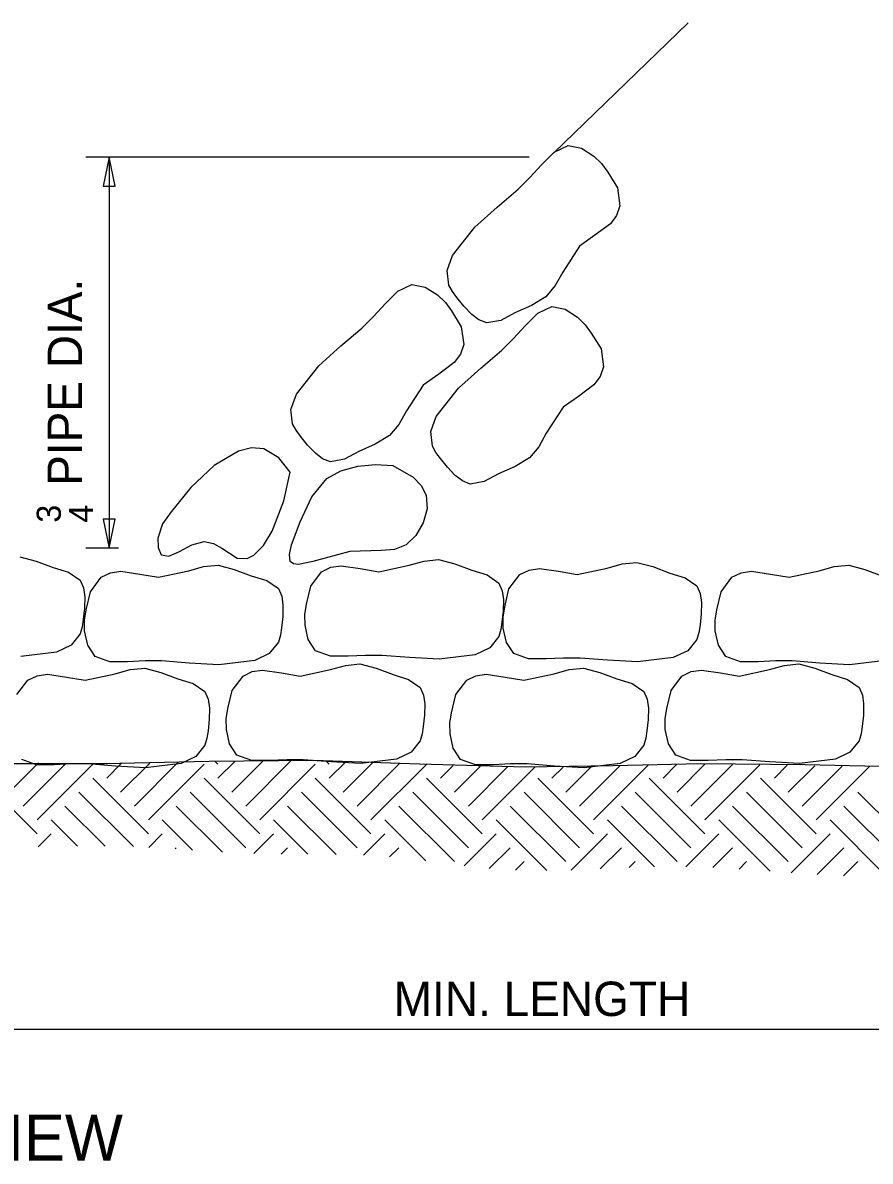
# Model space of a CAD drawing. Extents: x -439.1 to -407.9, y -458.1 to -436.2.
# Drawn here: x -428.606 to -424.913, y -444.35 to -439.387 of the extents above; entities that cross this region are included whole.
import ezdxf

# ---------------------------------------------------------------- set-up
doc = ezdxf.new("R2010")
doc.units = 0
doc.layers.add('Level 4', color=7, linetype='Continuous')

msp = doc.modelspace()

# ---------------------------------------------------------------- linework, layer by layer
at = {"layer": 'Level 4'}
for p, q in [((-426.2933, -439.9554), (-425.7067, -439.3867)), ((-426.3997, -439.973), (-428.3314, -439.973)), ((-428.2285, -439.973), (-428.2285, -441.6773)), ((-428.1891, -441.6773), (-428.3314, -441.6773)), ((-428.6643, -442.741), (-428.5371, -442.6138)), ((-428.1794, -442.741), (-428.0525, -442.6141)), ((-428.1187, -442.8016), (-427.9282, -442.6111)), ((-427.7551, -442.6197), (-427.7676, -442.6072)), ((-427.7551, -442.6804), (-427.6801, -442.6054)), ((-427.6944, -442.741), (-427.5572, -442.6037)), ((-427.6338, -442.8016), (-427.4355, -442.6033)), ((-427.2701, -442.6197), (-427.2849, -442.6049)), ((-427.2701, -442.6804), (-427.1967, -442.6069)), ((-427.2095, -442.741), (-427.0795, -442.611)), ((-428.6037, -442.8016), (-428.4176, -442.6156)), ((-428.543, -442.8622), (-428.3006, -442.6197)), ((-428.24, -442.6197), (-428.2417, -442.618)), ((-428.24, -442.6804), (-428.1764, -442.6168)), ((-428.0581, -442.8622), (-427.8157, -442.6197)), ((-427.5732, -442.8622), (-427.3308, -442.6197)), ((-427.1489, -442.8016), (-426.9629, -442.6155)), ((-427.0883, -442.8622), (-426.8464, -442.6203)), ((-426.7852, -442.6804), (-426.7299, -442.625)), ((-426.7246, -442.741), (-426.6124, -442.6288)), ((-426.664, -442.8016), (-426.4938, -442.6313)), ((-426.6034, -442.8622), (-426.3736, -442.6324)), ((-426.3003, -442.6804), (-426.2515, -442.6316)), ((-426.2397, -442.741), (-426.1279, -442.6292)), ((-426.1791, -442.8016), (-426.0036, -442.6261)), ((-426.1185, -442.8622), (-425.879, -442.6227)), ((-425.8154, -442.6804), (-425.7549, -442.6198)), ((-425.7548, -442.741), (-425.6323, -442.6184)), ((-425.6942, -442.8016), (-425.5129, -442.6203)), ((-425.6336, -442.8622), (-425.3936, -442.6222)), ((-425.3305, -442.6804), (-425.2743, -442.6241)), ((-425.2699, -442.741), (-425.1549, -442.626)), ((-425.2093, -442.8016), (-425.0356, -442.6279)), ((-425.1487, -442.8622), (-424.9163, -442.6298)), ((-428.543, -442.9228), (-428.7855, -442.6804)), ((-428.0581, -442.9228), (-428.3006, -442.6804)), ((-427.5732, -442.9228), (-427.8157, -442.6804)), ((-427.0883, -442.9228), (-427.3308, -442.6804)), ((-426.6034, -442.9228), (-426.8458, -442.6804)), ((-426.1185, -442.9228), (-426.3609, -442.6804)), ((-425.6336, -442.9228), (-425.876, -442.6804)), ((-425.1487, -442.9228), (-425.3911, -442.6804)), ((-428.1234, -442.9787), (-428.3612, -442.741)), ((-427.6338, -442.9834), (-427.8763, -442.741)), ((-427.1489, -442.9834), (-427.3914, -442.741)), ((-426.664, -442.9834), (-426.9065, -442.741)), ((-426.1791, -442.9834), (-426.4215, -442.741)), ((-425.6942, -442.9834), (-425.9366, -442.741)), ((-425.2093, -442.9834), (-425.4517, -442.741)), ((-424.7244, -442.9834), (-424.9668, -442.741)), ((-428.2468, -442.9766), (-428.4218, -442.8016)), ((-427.7356, -443.0029), (-427.9369, -442.8016)), ((-427.2407, -443.0128), (-427.452, -442.8016)), ((-426.7246, -443.044), (-426.9671, -442.8016)), ((-426.2397, -443.044), (-426.4822, -442.8016)), ((-425.7548, -443.044), (-425.9972, -442.8016)), ((-425.2699, -443.044), (-425.5123, -442.8016)), ((-424.785, -443.044), (-425.0274, -442.8016)), ((-428.3675, -442.9772), (-428.4824, -442.8622)), ((-427.8656, -442.9941), (-427.9975, -442.8622)), ((-427.3632, -443.0117), (-427.5126, -442.8622)), ((-426.8488, -443.0411), (-427.0277, -442.8622)), ((-426.3216, -443.0834), (-426.5428, -442.8622)), ((-425.853, -443.0671), (-426.0579, -442.8622)), ((-425.3493, -443.0858), (-425.5729, -442.8622)), ((-424.8456, -443.1047), (-425.088, -442.8622)), ((-428.5388, -442.9792), (-428.4824, -442.9228)), ((-428.0565, -442.9818), (-427.9975, -442.9228)), ((-427.5985, -443.0087), (-427.5126, -442.9228)), ((-427.1213, -443.0164), (-427.0277, -442.9228)), ((-426.6822, -443.0622), (-426.5428, -442.9228)), ((-426.2163, -443.0813), (-426.0579, -442.9228)), ((-425.7166, -443.0665), (-425.5729, -442.9228)), ((-425.2578, -443.0926), (-425.088, -442.9228)), ((-427.9421, -442.9887), (-427.9369, -442.9834)), ((-427.4795, -443.0109), (-427.452, -442.9834)), ((-427.0072, -443.0236), (-426.9671, -442.9834)), ((-426.5727, -443.0739), (-426.4822, -442.9834)), ((-426.0897, -443.0759), (-425.9972, -442.9834)), ((-425.5989, -443.07), (-425.5123, -442.9834)), ((-425.1443, -443.1003), (-425.0274, -442.9834)), ((-426.4586, -443.0811), (-426.4215, -443.044)), ((-425.9629, -443.0704), (-425.9366, -443.044)), ((-425.484, -443.0763), (-425.4517, -443.044)), ((-425.029, -443.1062), (-424.9668, -443.044)), ((-431.8697, -443.7744), (-420.5223, -443.7744))]:
    msp.add_line(p, q, dxfattribs=at)
for points in [[(-426.0567, -440.038), (-426.0141, -440.1066), (-426.0033, -440.1844), (-426.018, -440.2267), (-426.0451, -440.2634), (-426.1124, -440.3132), (-426.1799, -440.3609), (-426.253, -440.4735), (-426.2856, -440.5328), (-426.3263, -440.5817), (-426.3889, -440.6188), (-426.461, -440.6514), (-426.5232, -440.6841), (-426.5842, -440.6955), (-426.6181, -440.6819), (-426.6492, -440.6583), (-426.6836, -440.6226), (-426.7143, -440.584), (-426.7337, -440.5579), (-426.7491, -440.5306), (-426.7562, -440.467), (-426.7326, -440.4009), (-426.6353, -440.2773), (-426.5383, -440.1905), (-426.4471, -440.1123), (-426.3964, -440.0616), (-426.3448, -440.0055), (-426.2903, -439.9509), (-426.2287, -439.9218), (-426.1713, -439.9337), (-426.1171, -439.9683), (-426.0834, -440.0009), (-426.0567, -440.038)], [(-428.2023, -440.0995), (-428.2285, -439.973), (-428.2548, -440.0995)], [(-426.7376, -440.6432), (-426.695, -440.7118), (-426.6842, -440.7896), (-426.6989, -440.832), (-426.726, -440.8686), (-426.7933, -440.9184), (-426.8608, -440.9662), (-426.9339, -441.0788), (-426.9665, -441.138), (-427.0071, -441.1869), (-427.0698, -441.2241), (-427.1419, -441.2566), (-427.2041, -441.2893), (-427.2651, -441.3008), (-427.299, -441.2872), (-427.3301, -441.2636), (-427.3645, -441.2278), (-427.3952, -441.1892), (-427.4146, -441.1631), (-427.43, -441.1358), (-427.4371, -441.0723), (-427.4134, -441.0061), (-427.3162, -440.8825), (-427.2192, -440.7958), (-427.128, -440.7176), (-427.0773, -440.6668), (-427.0257, -440.6107), (-426.9712, -440.5562), (-426.9096, -440.5271), (-426.8522, -440.5389), (-426.798, -440.5735), (-426.7643, -440.6061), (-426.7376, -440.6432)], [(-426.1283, -440.7403), (-426.0857, -440.8089), (-426.0749, -440.8867), (-426.0896, -440.9291), (-426.1167, -440.9657), (-426.184, -441.0155), (-426.2514, -441.0633), (-426.3246, -441.1759), (-426.3572, -441.2351), (-426.3978, -441.284), (-426.4605, -441.3212), (-426.5326, -441.3537), (-426.5948, -441.3864), (-426.6557, -441.3979), (-426.6897, -441.3843), (-426.7208, -441.3607), (-426.7552, -441.3249), (-426.7858, -441.2864), (-426.8053, -441.2602), (-426.8207, -441.2329), (-426.8277, -441.1694), (-426.8041, -441.1033), (-426.7068, -440.9797), (-426.6098, -440.8929), (-426.5186, -440.8147), (-426.468, -440.7639), (-426.4164, -440.7078), (-426.3619, -440.6533), (-426.3002, -440.6242), (-426.2428, -440.636), (-426.1887, -440.6706), (-426.155, -440.7032), (-426.1283, -440.7403)], [(-427.4399, -441.3455), (-427.4904, -441.2842), (-427.5553, -441.2445), (-427.6093, -441.2397), (-427.6653, -441.2538), (-427.7717, -441.3166), (-427.8738, -441.4133), (-427.9593, -441.5186), (-427.9963, -441.5711), (-428.017, -441.634), (-428.0153, -441.6752), (-428.0025, -441.7062), (-427.9692, -441.7127), (-427.9224, -441.6917), (-427.8688, -441.6635), (-427.815, -441.6484), (-427.7745, -441.6567), (-427.7375, -441.6778), (-427.6707, -441.7206), (-427.6284, -441.7228), (-427.5983, -441.7082), (-427.5566, -441.6653), (-427.5195, -441.6038), (-427.4683, -441.4715), (-427.4399, -441.3455)], [(-426.9926, -441.3166), (-426.9052, -441.3682), (-426.8703, -441.4038), (-426.8484, -441.4465), (-426.8439, -441.506), (-426.8604, -441.5676), (-426.8924, -441.6228), (-426.9349, -441.6629), (-426.9865, -441.6828), (-427.0444, -441.6871), (-427.1802, -441.6917), (-427.341, -441.7353), (-427.4042, -441.7482), (-427.4262, -441.7458), (-427.4399, -441.735), (-427.4439, -441.7054), (-427.4347, -441.6628), (-427.3966, -441.5619), (-427.3463, -441.4529), (-427.2812, -441.3743), (-427.2193, -441.3399), (-427.1463, -441.3194), (-427.0685, -441.3119), (-426.9926, -441.3166)], [(-428.2548, -441.5508), (-428.2285, -441.6773), (-428.2023, -441.5508)], [(-428.3295, -441.9457), (-428.3111, -441.8671), (-428.2638, -441.8044), (-428.2234, -441.7849), (-428.1783, -441.7782), (-428.0955, -441.7905), (-428.014, -441.8044), (-427.8827, -441.7765), (-427.8177, -441.7577), (-427.7545, -441.7519), (-427.6839, -441.7699), (-427.6099, -441.7979), (-427.5427, -441.8187), (-427.4916, -441.8537), (-427.4772, -441.8873), (-427.4719, -441.926), (-427.4729, -441.9756), (-427.4784, -442.0246), (-427.4832, -442.0568), (-427.4916, -442.087), (-427.5315, -442.1369), (-427.595, -442.167), (-427.7512, -442.1856), (-427.8811, -442.1784), (-428.0009, -442.1692), (-428.0726, -442.1693), (-428.1488, -442.1725), (-428.2259, -442.1725), (-428.29, -442.1494), (-428.3223, -442.1005), (-428.3361, -442.0377), (-428.3369, -441.9908), (-428.3295, -441.9457)], [(-427.3689, -441.9214), (-427.3505, -441.8428), (-427.3032, -441.7801), (-427.2628, -441.7606), (-427.2177, -441.7538), (-427.1349, -441.7662), (-427.0534, -441.7801), (-426.9221, -441.7522), (-426.8571, -441.7334), (-426.7939, -441.7275), (-426.7233, -441.7456), (-426.6493, -441.7736), (-426.5821, -441.7944), (-426.531, -441.8294), (-426.5166, -441.863), (-426.5113, -441.9017), (-426.5123, -441.9513), (-426.5178, -442.0003), (-426.5226, -442.0325), (-426.531, -442.0627), (-426.5709, -442.1126), (-426.6344, -442.1427), (-426.7906, -442.1613), (-426.9205, -442.154), (-427.0403, -442.1448), (-427.112, -442.1449), (-427.1882, -442.1481), (-427.2653, -442.1481), (-427.3294, -442.1251), (-427.3617, -442.0762), (-427.3754, -442.0134), (-427.3762, -441.9665), (-427.3689, -441.9214)], [(-426.5056, -441.9336), (-426.4872, -441.8549), (-426.4398, -441.7923), (-426.3994, -441.7727), (-426.3544, -441.766), (-426.2716, -441.7783), (-426.1901, -441.7923), (-426.0588, -441.7644), (-425.9938, -441.7455), (-425.9305, -441.7397), (-425.8599, -441.7577), (-425.786, -441.7857), (-425.7188, -441.8066), (-425.6677, -441.8416), (-425.6533, -441.8752), (-425.6479, -441.9138), (-425.6489, -441.9635), (-425.6545, -442.0124), (-425.6593, -442.0446), (-425.6677, -442.0749), (-425.7076, -442.1248), (-425.7711, -442.1548), (-425.9272, -442.1734), (-426.0572, -442.1662), (-426.177, -442.157), (-426.2487, -442.1571), (-426.3248, -442.1603), (-426.4019, -442.1603), (-426.4661, -442.1373), (-426.4983, -442.0883), (-426.5121, -442.0256), (-426.5129, -441.9787), (-426.5056, -441.9336)], [(-427.7116, -442.3763), (-427.6933, -442.2977), (-427.6459, -442.235), (-427.6055, -442.2154), (-427.5605, -442.2087), (-427.4777, -442.221), (-427.3962, -442.235), (-427.2649, -442.2071), (-427.1999, -442.1883), (-427.1366, -442.1824), (-427.066, -442.2004), (-426.992, -442.2284), (-426.9249, -442.2493), (-426.8737, -442.2843), (-426.8594, -442.3179), (-426.854, -442.3566), (-426.855, -442.4062), (-426.8606, -442.4551), (-426.8654, -442.4874), (-426.8737, -442.5176), (-426.9137, -442.5675), (-426.9771, -442.5975), (-427.1333, -442.6161), (-427.2633, -442.6089), (-427.3831, -442.5997), (-427.4548, -442.5998), (-427.5309, -442.603), (-427.608, -442.603), (-427.6722, -442.58), (-427.7044, -442.531), (-427.7182, -442.4683), (-427.719, -442.4214), (-427.7116, -442.3763)], [(-426.737, -442.3947), (-426.7187, -442.316), (-426.6713, -442.2534), (-426.6309, -442.2338), (-426.5859, -442.2271), (-426.5031, -442.2394), (-426.4216, -442.2534), (-426.2903, -442.2255), (-426.2253, -442.2066), (-426.162, -442.2008), (-426.0914, -442.2188), (-426.0174, -442.2468), (-425.9503, -442.2677), (-425.8991, -442.3027), (-425.8847, -442.3363), (-425.8794, -442.3749), (-425.8804, -442.4246), (-425.886, -442.4735), (-425.8908, -442.5057), (-425.8991, -442.536), (-425.9391, -442.5858), (-426.0025, -442.6159), (-426.1587, -442.6345), (-426.2887, -442.6273), (-426.4084, -442.6181), (-426.4801, -442.6182), (-426.5563, -442.6214), (-426.6334, -442.6214), (-426.6976, -442.5984), (-426.7298, -442.5494), (-426.7436, -442.4867), (-426.7444, -442.4398), (-426.737, -442.3947)], [(-425.7992, -442.3763), (-425.7808, -442.2977), (-425.7335, -442.235), (-425.6931, -442.2154), (-425.6481, -442.2087), (-425.5652, -442.221), (-425.4838, -442.235), (-425.3524, -442.2071), (-425.2875, -442.1883), (-425.2242, -442.1824), (-425.1536, -442.2004), (-425.0796, -442.2284), (-425.0125, -442.2493), (-424.9613, -442.2843), (-424.9469, -442.3179), (-424.9416, -442.3566), (-424.9426, -442.4062), (-424.9482, -442.4551), (-424.9529, -442.4874), (-424.9613, -442.5176), (-425.0012, -442.5675), (-425.0647, -442.5975), (-425.2209, -442.6161), (-425.3509, -442.6089), (-425.4706, -442.5997), (-425.5423, -442.5998), (-425.6185, -442.603), (-425.6956, -442.603), (-425.7598, -442.58), (-425.792, -442.531), (-425.8058, -442.4683), (-425.8066, -442.4214), (-425.7992, -442.3763)]]:
    msp.add_lwpolyline(points, close=True, dxfattribs=at)
for points in [[(-428.6178, -441.7154), (-428.5472, -441.7334), (-428.4732, -441.7614), (-428.4061, -441.7823), (-428.3549, -441.8172), (-428.3405, -441.8509), (-428.3352, -441.8895), (-428.3362, -441.9391), (-428.3418, -441.9881), (-428.3465, -442.0203), (-428.3549, -442.0505), (-428.3948, -442.1004), (-428.4583, -442.1305), (-428.6145, -442.1491)], [(-424.8469, -442.167), (-425.0031, -442.1856), (-425.1331, -442.1784), (-425.2528, -442.1692), (-425.3246, -442.1693), (-425.4007, -442.1725), (-425.4778, -442.1725), (-425.542, -442.1494), (-425.5742, -442.1005), (-425.588, -442.0377), (-425.5888, -441.9908), (-425.5814, -441.9457), (-425.5814, -441.9457), (-425.5631, -441.8671), (-425.5157, -441.8044), (-425.4753, -441.7849), (-425.4303, -441.7782), (-425.3475, -441.7905), (-425.266, -441.8044), (-425.1347, -441.7765), (-425.0697, -441.7577), (-425.0064, -441.7519), (-424.9358, -441.7699), (-424.8618, -441.7979)], [(-428.6311, -442.316), (-428.5838, -442.2534), (-428.5434, -442.2338), (-428.4983, -442.2271), (-428.4155, -442.2394), (-428.334, -442.2534), (-428.2027, -442.2255), (-428.1377, -442.2066), (-428.0744, -442.2008), (-428.0039, -442.2188), (-427.9299, -442.2468), (-427.8627, -442.2677), (-427.8116, -442.3027), (-427.7972, -442.3363), (-427.7919, -442.3749), (-427.7929, -442.4246), (-427.7984, -442.4735), (-427.8032, -442.5057), (-427.8116, -442.536), (-427.8515, -442.5858), (-427.915, -442.6159), (-428.0712, -442.6345), (-428.2011, -442.6273), (-428.3209, -442.6181), (-428.3926, -442.6182), (-428.4688, -442.6214), (-428.5459, -442.6214), (-428.61, -442.5984)], [(-424.7422, -442.6326), (-425.1968, -442.622), (-425.6511, -442.6181), (-426.0334, -442.6269), (-426.4158, -442.6326), (-426.8775, -442.6191), (-427.3391, -442.6037), (-427.7935, -442.6077), (-428.2481, -442.6181), (-428.7243, -442.6177), (-429.2003, -442.6037), (-429.6837, -442.5801), (-430.1669, -442.5604), (-430.5634, -442.556), (-430.9604, -442.5604), (-431.3146, -442.5644), (-431.6674, -442.546), (-431.7686, -442.5331), (-431.8694, -442.5172)]]:
    msp.add_lwpolyline(points, dxfattribs=at)

# ---------------------------------------------------------------- texts
for s, height, p in [(' PIPE DIA.', 0.15, (-428.3474, -441.4613)), ('3', 0.105, (-428.4399, -441.5663)), ('4', 0.105, (-428.2999, -441.5663))]:
    msp.add_text(s, height=height, rotation=90, dxfattribs=at).set_placement(p)
for s, height, p in [('MIN. LENGTH', 0.15, (-426.9897, -443.7173)), ('SIDE VIEW', 0.2, (-429.5514, -444.3475))]:
    msp.add_text(s, height=height, dxfattribs=at).set_placement(p)

doc.saveas('drawing.dxf')
